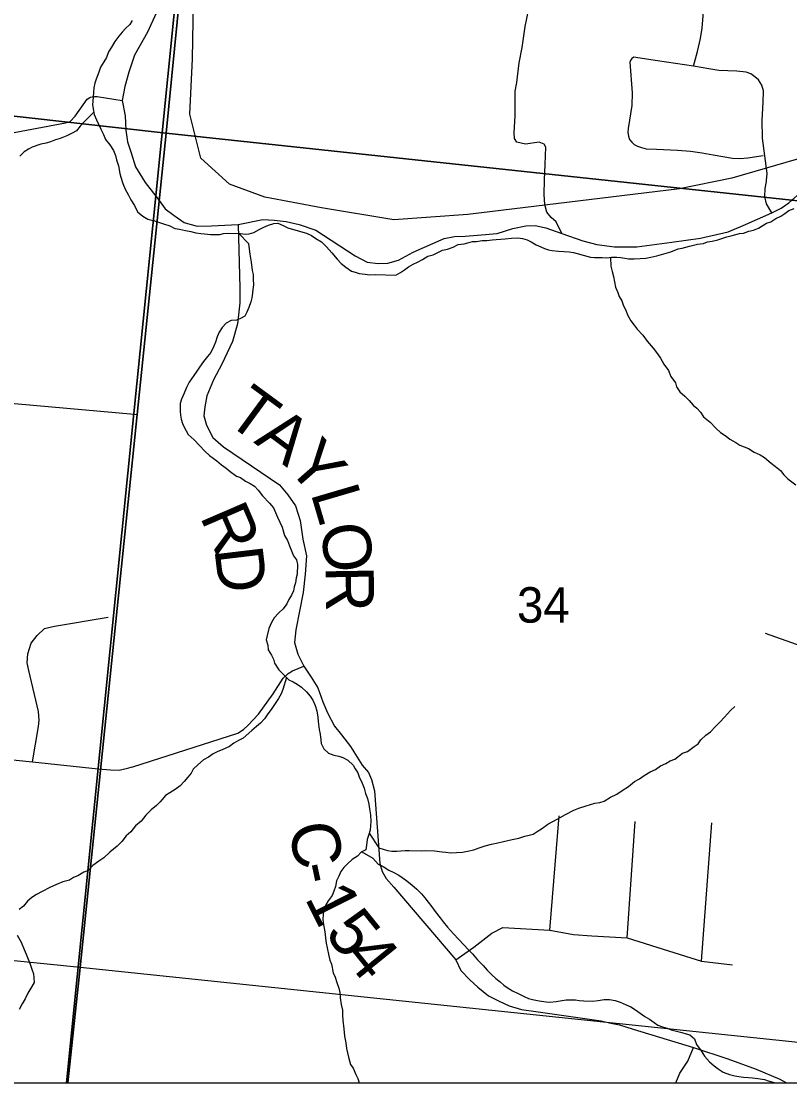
# Model space of a CAD drawing. Extents: x 0 to 34, y 0 to 22.
# Drawn here: x 5.013 to 5.92, y 14.1 to 15.353 of the extents above; entities that cross this region are included whole.
import ezdxf

# ---------------------------------------------------------------- set-up
doc = ezdxf.new("R2010")
doc.units = 0
for name, color, linetype in [('Default', 7, 'Continuous'), ('GM_X_County_Road', 7, 'Continuous'), ('GM_X_County_Road_Text', 7, 'Continuous'), ('GM_X_Minor_River', 7, 'Continuous'), ('GM_X_Rail_Line', 7, 'Continuous'), ('GM_X_Section', 7, 'Continuous'), ('GM_X_Section_Text', 7, 'Continuous'), ('GM_X_State_Route', 7, 'Continuous'), ('GM_X_Township_Road', 7, 'Continuous'), ('SH_Data', 7, 'Continuous')]:
    doc.layers.add(name, color=color, linetype=linetype)

msp = doc.modelspace()

# ---------------------------------------------------------------- linework, layer by layer
at = {"layer": 'Default'}
for points in [[(4.0529, 14.1), (5.0677, 14.1), (5.0822, 14.236), (4.0766, 14.3377)], [(5.0677, 14.1), (6.0771, 14.1), (6.0802, 14.1319), (5.0822, 14.236)]]:
    msp.add_lwpolyline(points, close=True, dxfattribs=at)
at = {"layer": 'GM_X_County_Road'}
for points in [[(5.1803, 15.4536), (5.1836, 15.4413), (5.1869, 15.4215), (5.1859, 15.3991), (5.1817, 15.3837), (5.172, 15.3623), (5.1619, 15.3401), (5.1464, 15.3128), (5.1398, 15.2929), (5.1351, 15.2759), (5.132, 15.2596), (5.1353, 15.2413), (5.1364, 15.2242), (5.1383, 15.2105), (5.1425, 15.1978), (5.1477, 15.181), (5.159, 15.1625), (5.1717, 15.1463), (5.1755, 15.1415), (5.1828, 15.1315), (5.1933, 15.1236), (5.2052, 15.1153), (5.2062, 15.115)], [(4.6816, 15.2761), (4.9391, 15.2431), (4.9463, 15.2402), (4.9567, 15.2324), (4.9682, 15.2245), (4.9784, 15.2204), (4.992, 15.2193), (5.0649, 15.2329), (5.0706, 15.2347), (5.0765, 15.241), (5.0907, 15.2611), (5.0938, 15.2628), (5.0947, 15.2632), (5.0965, 15.2639), (5.0994, 15.2642), (5.1025, 15.2642), (5.132, 15.2596)], [(5.2689, 15.1129), (5.2979, 15.1189), (5.3112, 15.1182), (5.3252, 15.1167), (5.3406, 15.1129), (5.3602, 15.1063), (5.4068, 15.0762), (5.421, 15.0686), (5.4339, 15.0671), (5.4453, 15.0676), (5.4579, 15.071), (5.4753, 15.0805), (5.5118, 15.0966), (5.524, 15.0989), (5.5365, 15.0994), (5.5513, 15.1005), (5.5742, 15.1025), (5.5929, 15.1085), (5.6082, 15.1115), (5.6192, 15.112), (5.6317, 15.109), (5.6508, 15.1023), (5.6753, 15.0938), (5.6919, 15.0896), (5.7127, 15.0867), (5.7389, 15.0868), (5.7804, 15.0922), (5.8143, 15.097), (5.8468, 15.1045), (5.8644, 15.112), (5.8982, 15.1268), (5.9095, 15.1325), (5.9183, 15.1385), (5.9517, 15.1682)], [(5.2062, 15.115), (5.2203, 15.1111), (5.2373, 15.1114), (5.2689, 15.1129)], [(5.2689, 15.1129), (5.2707, 15.038), (5.2706, 15.0205), (5.268, 14.9959), (5.2621, 14.9748), (5.2496, 14.9482), (5.2397, 14.9298), (5.2319, 14.911), (5.2293, 14.8978), (5.2283, 14.8872), (5.2314, 14.8761), (5.239, 14.8618), (5.2516, 14.8505), (5.3175, 14.8058), (5.3275, 14.7938), (5.3362, 14.781), (5.3418, 14.7638), (5.345, 14.7417), (5.3494, 14.7218), (5.3477, 14.7002), (5.3456, 14.6786), (5.3368, 14.6348), (5.3353, 14.6196), (5.3391, 14.6059), (5.3461, 14.5919), (5.3547, 14.5789), (5.3627, 14.5661), (5.3687, 14.5496), (5.374, 14.5366), (5.3823, 14.5208), (5.3908, 14.5107), (5.4014, 14.4971), (5.4152, 14.4747), (5.4226, 14.4662), (5.4262, 14.4581), (5.4296, 14.4447), (5.436, 14.3587), (5.4388, 14.3495), (5.4435, 14.341), (5.4523, 14.3309), (5.5254, 14.2451), (5.5313, 14.2327), (5.542, 14.2214), (5.5516, 14.2128), (5.5639, 14.2026), (5.5766, 14.1962), (5.5886, 14.1909), (5.6029, 14.1864), (5.6199, 14.1841), (5.6971, 14.1733), (5.7084, 14.1703), (5.7186, 14.1682), (5.7348, 14.1632), (5.8059, 14.1415)], [(5.1427, 14.4726), (5.1445, 14.4731), (5.2682, 14.5128), (5.2749, 14.517), (5.2806, 14.5219), (5.2927, 14.5349), (5.3101, 14.5591), (5.322, 14.5774), (5.3278, 14.5829), (5.3328, 14.5863), (5.3461, 14.5919)], [(4.8992, 14.4919), (5.026, 14.4788), (5.1037, 14.4707), (5.1182, 14.4692), (5.1285, 14.469), (5.1398, 14.4719), (5.1427, 14.4726)], [(5.785, 14.1), (5.7899, 14.1112), (5.7994, 14.1254), (5.8059, 14.1415)], [(5.8059, 14.1415), (5.8466, 14.1283), (5.88, 14.116), (5.9078, 14.1043), (5.9157, 14.1)]]:
    msp.add_lwpolyline(points, dxfattribs=at)
at = {"layer": 'GM_X_Minor_River'}
for points in [[(5.1437, 15.3537), (5.1409, 15.3493), (5.1358, 15.3445), (5.1318, 15.3401), (5.1279, 15.3353), (5.1231, 15.329), (5.1195, 15.3223), (5.1159, 15.3167), (5.1133, 15.31), (5.1101, 15.3051), (5.1065, 15.2988), (5.1044, 15.2928)], [(5.1044, 15.2928), (5.1011, 15.2845), (5.0998, 15.28), (5.0985, 15.2744), (5.0979, 15.2687), (5.0977, 15.2638), (5.0972, 15.2588), (5.097, 15.2543), (5.0979, 15.2478), (5.0989, 15.2428), (5.1017, 15.2367), (5.1038, 15.2313), (5.1066, 15.2255), (5.1098, 15.2193), (5.1123, 15.2135), (5.1174, 15.2069), (5.1217, 15.2003), (5.1242, 15.1945), (5.1251, 15.1895), (5.1276, 15.1822), (5.1292, 15.1734), (5.1305, 15.1688), (5.1325, 15.1615), (5.1354, 15.1549), (5.1393, 15.1476), (5.1421, 15.1422), (5.1465, 15.1356), (5.15, 15.1279), (5.1563, 15.1227), (5.1622, 15.1194), (5.1701, 15.1173), (5.1761, 15.1155), (5.1806, 15.1139), (5.1881, 15.1113), (5.1941, 15.1085), (5.1994, 15.1075), (5.2066, 15.1058), (5.213, 15.1048), (5.219, 15.1034), (5.2247, 15.1025), (5.2292, 15.1019), (5.236, 15.1013), (5.2413, 15.1011), (5.247, 15.1013), (5.2516, 15.1023), (5.2569, 15.1029), (5.2714, 15.1024), (5.277, 15.1018), (5.2816, 15.102), (5.2874, 15.1037), (5.2935, 15.1073), (5.2989, 15.1098), (5.3047, 15.1122), (5.3109, 15.1143), (5.3154, 15.1145), (5.3218, 15.1117), (5.3274, 15.1092), (5.3342, 15.1071), (5.3492, 15.1027), (5.3552, 15.0999), (5.3604, 15.0966), (5.3671, 15.0926), (5.3729, 15.0867), (5.3792, 15.0797), (5.3854, 15.0722), (5.3901, 15.0671), (5.3957, 15.0628), (5.4023, 15.058), (5.4068, 15.0567), (5.4117, 15.0554), (5.4185, 15.0544), (5.4242, 15.0538), (5.4307, 15.0539), (5.4549, 15.0531), (5.4604, 15.0563), (5.465, 15.0596), (5.4697, 15.0632), (5.4751, 15.0661), (5.4805, 15.0686), (5.4863, 15.0718), (5.4925, 15.0757), (5.4987, 15.0774), (5.5037, 15.0795), (5.5099, 15.0827), (5.5156, 15.0841), (5.5225, 15.0861), (5.5283, 15.0893), (5.5352, 15.0902), (5.5398, 15.0916), (5.5451, 15.0929), (5.5501, 15.0928), (5.5566, 15.094), (5.5623, 15.0942), (5.5684, 15.0948), (5.5733, 15.0954), (5.5787, 15.0959), (5.5836, 15.0962), (5.5912, 15.097), (5.5988, 15.0972), (5.6041, 15.0966), (5.6098, 15.0949)], [(5.0983, 15.2458), (5.0868, 15.2338), (5.0825, 15.229), (5.0781, 15.2238), (5.0731, 15.2209), (5.0665, 15.2177), (5.0588, 15.2146), (5.0534, 15.2129), (5.0473, 15.2108), (5.0423, 15.2091), (5.0358, 15.2078), (5.0258, 15.2043), (5.0212, 15.2018), (5.0161, 15.199), (5.011, 15.1938)], [(5.6098, 15.0949), (5.6146, 15.0924), (5.6202, 15.0892), (5.6258, 15.0867), (5.6303, 15.0847), (5.6348, 15.083), (5.6393, 15.0825), (5.6465, 15.0814), (5.6529, 15.0812), (5.6594, 15.0806), (5.6643, 15.0801), (5.6688, 15.0788), (5.6756, 15.077), (5.6846, 15.0744), (5.6891, 15.0739), (5.6983, 15.074), (5.7036, 15.0738), (5.7093, 15.0743), (5.7154, 15.0745), (5.7203, 15.074), (5.7248, 15.0734), (5.7293, 15.0725), (5.7358, 15.0727), (5.743, 15.0728), (5.7499, 15.0733), (5.7556, 15.0746), (5.7625, 15.0759), (5.7709, 15.0783), (5.7794, 15.0807), (5.7878, 15.0845), (5.7924, 15.0851), (5.8012, 15.0875), (5.8058, 15.0885), (5.8108, 15.0898), (5.8177, 15.0907), (5.8223, 15.0925), (5.828, 15.0934), (5.8345, 15.0951), (5.8453, 15.0985), (5.8514, 15.1002), (5.8602, 15.1026), (5.8648, 15.1028), (5.8713, 15.1052), (5.8767, 15.1062), (5.8828, 15.1086), (5.8921, 15.1148), (5.8971, 15.1161), (5.903, 15.1201), (5.9088, 15.1229), (5.9138, 15.1262), (5.9185, 15.1294), (5.9246, 15.1319)], [(5.2697, 15.1024), (5.2808, 15.0907), (5.2817, 15.0838), (5.2827, 15.0781), (5.2833, 15.0735), (5.2839, 15.0685), (5.2854, 15.0586), (5.2864, 15.054), (5.2866, 15.0483), (5.2867, 15.0418), (5.2862, 15.0365), (5.2856, 15.032), (5.2847, 15.0263), (5.2838, 15.0218), (5.2813, 15.015), (5.2788, 15.0094), (5.2767, 15.0049), (5.2717, 15.0021), (5.2667, 15), (5.2606, 14.9998), (5.2544, 14.9966), (5.2497, 14.9914), (5.2465, 14.9858), (5.244, 14.9806), (5.2419, 14.9742), (5.2402, 14.9693), (5.2365, 14.9619), (5.2326, 14.9574), (5.2278, 14.9515), (5.223, 14.9445), (5.2198, 14.94), (5.2166, 14.9348), (5.211, 14.927), (5.2078, 14.9207), (5.2049, 14.9139), (5.202, 14.9068), (5.2003, 14.9016), (5.2004, 14.8928), (5.2006, 14.8879), (5.2016, 14.8833), (5.2029, 14.8783), (5.205, 14.8737), (5.2097, 14.8651), (5.2167, 14.8588), (5.2233, 14.8521), (5.2295, 14.8455), (5.235, 14.8403), (5.2435, 14.834), (5.2491, 14.8292), (5.2546, 14.8256), (5.2594, 14.8216), (5.2668, 14.8161), (5.2717, 14.8144), (5.2773, 14.81), (5.2829, 14.8075), (5.2881, 14.8043), (5.2925, 14.7996), (5.2975, 14.7926), (5.3056, 14.7843), (5.3104, 14.7788), (5.3128, 14.7731), (5.3153, 14.7677), (5.3206, 14.7557), (5.3233, 14.7461), (5.3269, 14.7399), (5.3293, 14.7337), (5.3318, 14.7279), (5.3342, 14.7218), (5.3375, 14.7171), (5.3388, 14.7117), (5.3384, 14.7004), (5.3371, 14.6958), (5.3365, 14.6902), (5.3348, 14.6853), (5.3339, 14.6808), (5.3315, 14.6755), (5.3286, 14.6703), (5.3262, 14.6654), (5.3218, 14.6595), (5.3167, 14.6548), (5.3112, 14.6489), (5.308, 14.6433), (5.3051, 14.6362), (5.3029, 14.6279), (5.3019, 14.623), (5.3036, 14.6164), (5.3042, 14.6111), (5.3082, 14.6049), (5.3103, 14.5999), (5.3116, 14.5953), (5.3167, 14.5875), (5.3233, 14.5808), (5.3284, 14.5757), (5.3336, 14.5732), (5.3385, 14.5704), (5.3433, 14.5668), (5.3492, 14.5613), (5.3536, 14.5562), (5.3568, 14.5515), (5.3596, 14.5454), (5.3617, 14.5392)], [(5.7081, 15.0742), (5.7085, 15.0637), (5.7098, 15.0576), (5.7115, 15.0515), (5.7141, 15.0392), (5.7166, 15.0327), (5.7183, 15.0281), (5.7212, 15.023), (5.7233, 15.0172), (5.7258, 15.0126), (5.7286, 15.0057), (5.7321, 14.9995), (5.7358, 14.9944), (5.7394, 14.9897), (5.746, 14.9826), (5.7511, 14.9753), (5.7584, 14.967), (5.7635, 14.9604), (5.7671, 14.9553), (5.771, 14.9483), (5.7764, 14.9409), (5.7792, 14.9336), (5.7847, 14.9262), (5.786, 14.9216), (5.79, 14.9154), (5.7959, 14.9103), (5.8007, 14.9055), (5.8054, 14.8997), (5.8098, 14.8961), (5.8142, 14.8914), (5.8178, 14.8859), (5.8256, 14.8796), (5.8322, 14.8725), (5.8377, 14.8674), (5.8444, 14.8634), (5.8488, 14.8598), (5.8559, 14.8558), (5.8607, 14.8525), (5.8709, 14.8488), (5.8775, 14.8444), (5.8846, 14.8411), (5.8899, 14.8382), (5.8976, 14.8315), (5.9028, 14.8275), (5.9087, 14.8228), (5.9127, 14.8177), (5.9171, 14.813), (5.9267, 14.8058)], [(5.3258, 14.5783), (5.3216, 14.5641), (5.3195, 14.5589), (5.3163, 14.5537), (5.3115, 14.5463), (5.3083, 14.5418), (5.3031, 14.5344), (5.2999, 14.5296), (5.2951, 14.5244), (5.2904, 14.5204), (5.285, 14.5156), (5.2748, 14.5069), (5.269, 14.504), (5.2636, 14.5008), (5.2585, 14.4968), (5.25, 14.4929), (5.2446, 14.4912), (5.2392, 14.4883), (5.2338, 14.4843), (5.228, 14.4811), (5.2213, 14.4753), (5.2158, 14.4701), (5.2134, 14.4653), (5.2094, 14.4609), (5.2051, 14.4557), (5.2003, 14.4505), (5.1945, 14.4462), (5.1883, 14.4422), (5.1832, 14.439), (5.1769, 14.4316), (5.1726, 14.4272), (5.1663, 14.4221), (5.16, 14.4158), (5.1545, 14.4088), (5.1478, 14.4033), (5.1423, 14.3963), (5.1368, 14.3916), (5.1316, 14.3849), (5.1261, 14.3794), (5.1175, 14.3721), (5.1101, 14.3655), (5.1043, 14.3615), (5.0973, 14.3564), (5.0913, 14.3502), (5.0867, 14.3484), (5.0794, 14.3441), (5.0744, 14.3424), (5.0697, 14.3392), (5.062, 14.3371), (5.0543, 14.334), (5.0466, 14.3304), (5.0377, 14.3258), (5.0308, 14.3223), (5.0253, 14.3186), (5.0202, 14.3143), (5.0155, 14.3083), (5.0104, 14.3047)], [(5.3617, 14.5392), (5.3626, 14.5316), (5.3632, 14.5266), (5.3644, 14.5171), (5.3653, 14.5113), (5.3662, 14.5048), (5.3668, 14.5003), (5.37, 14.4941), (5.3755, 14.4889), (5.3815, 14.4868), (5.3876, 14.4855), (5.3921, 14.4838), (5.398, 14.4809), (5.4043, 14.475), (5.4068, 14.4704), (5.4101, 14.4657), (5.4114, 14.4611), (5.415, 14.4538), (5.4174, 14.4476), (5.4191, 14.4415), (5.4212, 14.4357), (5.4228, 14.4288), (5.4238, 14.4234), (5.4247, 14.4162), (5.4252, 14.4082), (5.425, 14.4036), (5.4244, 14.398), (5.4227, 14.3919), (5.421, 14.3871), (5.42, 14.3806), (5.4195, 14.375), (5.414, 14.3721), (5.4097, 14.3673), (5.4031, 14.3634), (5.3976, 14.3586), (5.3933, 14.3542), (5.3897, 14.3494), (5.3876, 14.3438), (5.3848, 14.3382), (5.3834, 14.3317), (5.3817, 14.3261), (5.3796, 14.3212), (5.3749, 14.3149), (5.372, 14.3101), (5.37, 14.3052), (5.369, 14.2988), (5.3688, 14.2931), (5.3693, 14.2866), (5.3706, 14.2805), (5.3712, 14.2752), (5.3718, 14.2706), (5.3724, 14.2649), (5.3737, 14.2591), (5.3757, 14.2499), (5.377, 14.2446), (5.3787, 14.2399), (5.3807, 14.2296), (5.3831, 14.2246), (5.3852, 14.2184), (5.3876, 14.2115), (5.3886, 14.2065), (5.3891, 14.2001), (5.3904, 14.1924), (5.3917, 14.1855), (5.3918, 14.1798), (5.3924, 14.1737), (5.3936, 14.1638), (5.3944, 14.155), (5.3957, 14.147), (5.3966, 14.1405), (5.3989, 14.1302), (5.4012, 14.1217), (5.4045, 14.1171), (5.4077, 14.1097), (5.4098, 14.1051), (5.4117, 14.1)], [(5.4235, 14.3948), (5.4347, 14.3775), (5.44, 14.3758), (5.4449, 14.3741), (5.4502, 14.3735), (5.4558, 14.3733), (5.4608, 14.3739), (5.4657, 14.3741), (5.4703, 14.3743), (5.4847, 14.3738), (5.49, 14.374), (5.5003, 14.3737), (5.5094, 14.3726), (5.5139, 14.3721), (5.5196, 14.3715), (5.5264, 14.3716), (5.5333, 14.3722), (5.5394, 14.3735), (5.5466, 14.3751), (5.5532, 14.3772), (5.5601, 14.3796), (5.5678, 14.3816), (5.575, 14.3833), (5.5819, 14.3849), (5.5922, 14.3872), (5.5999, 14.3889), (5.6068, 14.3909), (5.6122, 14.3922), (5.6168, 14.3936), (5.6214, 14.3965), (5.6265, 14.3997), (5.6342, 14.4052), (5.6393, 14.408), (5.6459, 14.4116), (5.6551, 14.4166), (5.6648, 14.4216), (5.6706, 14.424), (5.6794, 14.4268), (5.6894, 14.4299), (5.6955, 14.4308), (5.7005, 14.4325), (5.7082, 14.4372), (5.7156, 14.4407), (5.7218, 14.4451), (5.7292, 14.4498), (5.7362, 14.4556), (5.7424, 14.4588), (5.7478, 14.4628), (5.7548, 14.4671), (5.761, 14.4699), (5.7672, 14.4739), (5.7734, 14.4767), (5.7784, 14.48), (5.7838, 14.4821), (5.7928, 14.489), (5.7989, 14.491), (5.8067, 14.4969), (5.8114, 14.5001), (5.8146, 14.5049), (5.8205, 14.5104), (5.8259, 14.5144), (5.8319, 14.5207), (5.837, 14.5258), (5.8425, 14.5317), (5.8496, 14.5395), (5.8547, 14.5442)], [(5.4146, 14.3724), (5.4275, 14.3652), (5.4341, 14.3581), (5.4397, 14.3553), (5.4467, 14.3508), (5.4523, 14.348), (5.4583, 14.3451), (5.4661, 14.3395), (5.4738, 14.3336), (5.4797, 14.3284), (5.4852, 14.3229), (5.4889, 14.3182), (5.4929, 14.3131), (5.4972, 14.3077), (5.5012, 14.3022), (5.507, 14.2948), (5.5107, 14.2901), (5.5158, 14.2835), (5.5227, 14.2756), (5.5407, 14.2564), (5.5451, 14.2521), (5.5513, 14.245), (5.5579, 14.2383), (5.5626, 14.2328), (5.5681, 14.2273), (5.5729, 14.223), (5.5777, 14.219), (5.5821, 14.2154), (5.5873, 14.2118), (5.5925, 14.2086), (5.5989, 14.2054), (5.606, 14.2017), (5.6112, 14.1996), (5.6161, 14.1983), (5.6237, 14.1969), (5.632, 14.1955), (5.6365, 14.1953), (5.6441, 14.1958), (5.6556, 14.1977), (5.6609, 14.1979), (5.6666, 14.1977), (5.6711, 14.1972), (5.6764, 14.1966), (5.6867, 14.1962), (5.6935, 14.1971), (5.7004, 14.1984), (5.7068, 14.1982), (5.7136, 14.1972), (5.7196, 14.1951), (5.7264, 14.1918), (5.732, 14.1897), (5.7376, 14.1861), (5.7487, 14.1781), (5.7539, 14.1749), (5.7594, 14.1713), (5.7639, 14.1681), (5.7695, 14.166), (5.7748, 14.1643), (5.7796, 14.1626), (5.7845, 14.1613), (5.7921, 14.1592), (5.7973, 14.1578), (5.8018, 14.1565), (5.807, 14.1518), (5.8094, 14.1453), (5.8148, 14.1375), (5.8188, 14.1313), (5.8247, 14.1246), (5.8302, 14.1198), (5.835, 14.1163), (5.8409, 14.1126), (5.8484, 14.1097), (5.8548, 14.108), (5.8594, 14.1074), (5.865, 14.1065), (5.8707, 14.1063), (5.8756, 14.1057), (5.8817, 14.1051), (5.8896, 14.1037), (5.8941, 14.1024), (5.9013, 14.1003), (5.9018, 14.1)], [(5.0082, 14.2744), (5.0129, 14.2659), (5.0164, 14.2574), (5.0188, 14.2516), (5.0209, 14.2458), (5.0234, 14.24), (5.0255, 14.2339), (5.0272, 14.2285), (5.0278, 14.2239), (5.0279, 14.2182), (5.0243, 14.2115), (5.0207, 14.2056), (5.0174, 14.1992), (5.0138, 14.1933), (5.0105, 14.1865)]]:
    msp.add_lwpolyline(points, dxfattribs=at)
at = {"layer": 'GM_X_Rail_Line'}
msp.add_lwpolyline([(7.0591, 15.07), (6.9789, 15.1159), (6.6986, 15.2444), (6.606, 15.2829), (6.5231, 15.3006), (6.4237, 15.3057), (6.344, 15.296), (6.2408, 15.2754), (6.0967, 15.239), (5.8513, 15.1677), (5.7896, 15.155), (5.5397, 15.125), (5.4524, 15.1186), (5.3669, 15.1328), (5.3004, 15.1455), (5.2587, 15.1606), (5.2248, 15.1914), (5.2119, 15.2431), (5.2148, 15.3086), (5.2164, 15.3989)], dxfattribs=at)
at = {"layer": 'GM_X_Section'}
for points in [[(5.2813, 16.2088), (5.1838, 15.2208), (4.1746, 15.3336), (4.2789, 16.3058)], [(6.268, 16.1109), (6.1715, 15.1151), (5.1838, 15.2208), (5.2813, 16.2088)], [(5.1838, 15.2208), (5.0822, 14.236), (4.0766, 14.3377), (4.1746, 15.3336)], [(6.1715, 15.1151), (6.0802, 14.1319), (5.0822, 14.236), (5.1838, 15.2208)]]:
    msp.add_lwpolyline(points, close=True, dxfattribs=at)
at = {"layer": 'GM_X_State_Route'}
for points in [[(5.2499, 15.926), (5.1715, 15.1469), (5.1456, 14.8898), (5.1035, 14.4713), (5.0661, 14.1), (8.9, 14.1), (8.9, 16.8616)], [(2.1, 16.7408), (2.1, 14.1), (5.0661, 14.1), (5.1035, 14.4713), (5.1456, 14.8898), (5.1715, 15.1469), (5.2499, 15.926)]]:
    msp.add_lwpolyline(points, dxfattribs=at)
at = {"layer": 'GM_X_Township_Road'}
for p, q in [((5.6365, 14.2801), (5.6473, 14.4152)), ((5.7276, 14.2709), (5.7372, 14.4084)), ((5.8155, 14.2437), (5.8275, 14.4068))]:
    msp.add_line(p, q, dxfattribs=at)
for points in [[(5.8058, 15.2998), (5.8107, 15.3171), (5.8142, 15.3324), (5.816, 15.3448), (5.8199, 15.3889)], [(5.6508, 15.1023), (5.6438, 15.1163), (5.6379, 15.1212), (5.6331, 15.1276), (5.6305, 15.1365), (5.6299, 15.1483), (5.6301, 15.1658), (5.6311, 15.1837), (5.6319, 15.2044), (5.6299, 15.208), (5.624, 15.2101), (5.6076, 15.2079), (5.5977, 15.2102), (5.5946, 15.2146), (5.5944, 15.2214), (5.5955, 15.2412), (5.5956, 15.2599), (5.5957, 15.2703), (5.5976, 15.2805), (5.6001, 15.304), (5.6038, 15.322), (5.6072, 15.3467), (5.6154, 15.3848)], [(5.8922, 15.1648), (5.8929, 15.1731), (5.8873, 15.2148), (5.887, 15.2363), (5.8882, 15.2571), (5.8884, 15.2707), (5.8865, 15.2777), (5.8825, 15.2839), (5.8783, 15.2875), (5.8737, 15.2908), (5.8682, 15.2929), (5.8569, 15.2939), (5.836, 15.2948), (5.8239, 15.2969), (5.8058, 15.2998), (5.7633, 15.3064), (5.7404, 15.3099), (5.7357, 15.3105), (5.733, 15.3091), (5.7315, 15.3067), (5.7309, 15.3047), (5.7334, 15.2684), (5.733, 15.2535), (5.7289, 15.2263), (5.7285, 15.2218), (5.7291, 15.2175), (5.7304, 15.2135), (5.7331, 15.2103), (5.7359, 15.2074), (5.74, 15.2054), (5.7445, 15.2039), (5.75, 15.2025), (5.7623, 15.2019), (5.787, 15.2006), (5.8026, 15.1995), (5.816, 15.1978), (5.8292, 15.1951), (5.8518, 15.1913), (5.8609, 15.191), (5.8701, 15.1917), (5.8881, 15.1944)], [(5.8982, 15.1268), (5.892, 15.1376), (5.8901, 15.1459), (5.8904, 15.1555), (5.8921, 15.1637), (5.8922, 15.1648)], [(4.8895, 14.4929), (4.9349, 14.9044), (4.9369, 14.9059), (4.9403, 14.9066), (4.9471, 14.9067), (5.1459, 14.8893), (5.1505, 14.8889)], [(5.026, 14.4788), (5.0331, 14.5205), (5.0341, 14.528), (5.0332, 14.5383), (5.0216, 14.5865), (5.0199, 14.5957), (5.0206, 14.6063), (5.0247, 14.6187), (5.0315, 14.628), (5.0404, 14.6361), (5.0522, 14.6389), (5.1152, 14.6494)], [(6.0271, 14.5822), (6.0207, 14.5844), (5.8908, 14.6304)], [(5.5254, 14.2451), (5.5466, 14.2599), (5.5681, 14.2767), (5.5809, 14.2833), (5.6365, 14.2801), (5.6642, 14.2749), (5.686, 14.2735), (5.7276, 14.2709), (5.7764, 14.2558)], [(5.7764, 14.2558), (5.8155, 14.2437), (5.8519, 14.2393)]]:
    msp.add_lwpolyline(points, dxfattribs=at)
at = {"layer": 'SH_Data'}
msp.add_line((2.1, 14.1), (8.9, 14.1), dxfattribs=at)

# ---------------------------------------------------------------- texts
at = {"layer": 'GM_X_County_Road_Text'}
for s, rotation, p in [('T', 323.7155, (5.2522, 14.881)), ('A', 323.2082, (5.2863, 14.856)), ('Y', 311.3148, (5.3241, 14.8281)), ('L', 286.4058, (5.354, 14.7963)), ('R', 293.3221, (5.2232, 14.7687)), ('O', 277.374, (5.3655, 14.7578)), ('D', 276.8282, (5.2406, 14.73)), ('R', 270.887, (5.3718, 14.7099)), ('C', 280.28, (5.328, 14.4032)), ('-', 282.0745, (5.3367, 14.3557)), ('1', 296.6444, (5.3467, 14.3182)), ('5', 309.0137, (5.3696, 14.2759)), ('4', 309.0164, (5.3914, 14.249))]:
    msp.add_text(s, height=0.0568, rotation=rotation, dxfattribs=at).set_placement(p)
at = {"layer": 'GM_X_Section_Text'}
msp.add_text('34', height=0.04186, rotation=0, dxfattribs=at).set_placement((5.5977, 14.6431))

doc.saveas('drawing.dxf')
